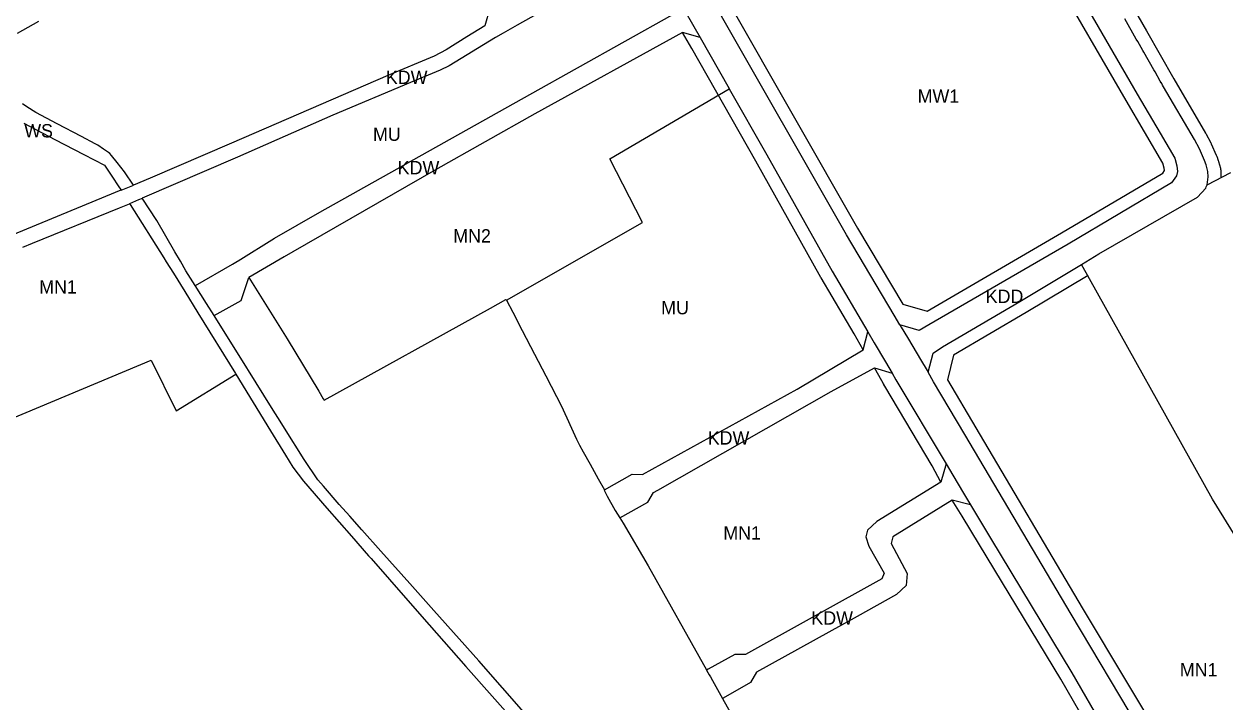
# Model space of a CAD drawing. Extents: x 7435758 to 7439981, y 5550649 to 5554049.
# Drawn here: x 7437381.1 to 7437849, y 5551344.8 to 5551609 of the extents above; entities that cross this region are included whole.
import ezdxf

# ---------------------------------------------------------------- set-up
doc = ezdxf.new("R2010")
doc.units = 0
for name, color, linetype in [('linie_rozgraniczające', 7, 'Continuous'), ('linie_zabudowy_nieprzekraczalne', 7, 'Continuous'), ('oznaczenia_przeznaczen', 7, 'Continuous')]:
    doc.layers.add(name, color=color, linetype=linetype)

msp = doc.modelspace()

# ---------------------------------------------------------------- linework, layer by layer
at = {"layer": 'linie_rozgraniczające'}
for p, q in [((7437608.04, 5551628.18), (7437573.23, 5551608.58)), ((7437791.88, 5551621.44), (7437814.86, 5551581.73)), ((7437562.56, 5551615.13), (7437560.61, 5551608.31)), ((7437638.09, 5551615.13), (7437642.09, 5551608.09)), ((7437701.57, 5551526.92), (7437651.34, 5551614.85)), ((7437578.11, 5551581.52), (7437633.83, 5551612.74)), ((7437814.48, 5551603.18), (7437810.02, 5551611.01)), ((7437560.61, 5551608.31), (7437553.64, 5551604.01)), ((7437567.77, 5551605.51), (7437564.75, 5551603.81)), ((7437573.23, 5551608.58), (7437567.77, 5551605.51)), ((7437637.67, 5551605.66), (7437580.13, 5551574.08)), ((7437644.58, 5551603.71), (7437637.67, 5551605.66)), ((7437642.09, 5551608.09), (7437644.58, 5551603.71)), ((7437553.64, 5551604.01), (7437545.49, 5551599)), ((7437564.75, 5551603.81), (7437546.77, 5551592.74)), ((7437644.58, 5551603.71), (7437655.83, 5551583.9)), ((7437815.05, 5551602.18), (7437814.48, 5551603.18)), ((7437816.99, 5551598.76), (7437815.05, 5551602.18)), ((7437540.86, 5551596.51), (7437522.88, 5551589.02)), ((7437545.49, 5551599), (7437540.86, 5551596.51)), ((7437817.4, 5551598.05), (7437816.99, 5551598.76)), ((7437821.35, 5551591.11), (7437817.4, 5551598.05)), ((7437546.77, 5551592.74), (7437543.25, 5551591.01)), ((7437522.88, 5551589.02), (7437461.88, 5551562.63)), ((7437543.25, 5551591.01), (7437531.66, 5551586.18)), ((7437821.79, 5551590.35), (7437821.35, 5551591.11)), ((7437823.82, 5551586.78), (7437821.79, 5551590.35)), ((7437824.19, 5551586.13), (7437823.82, 5551586.78)), ((7437531.66, 5551586.18), (7437501.44, 5551573.48)), ((7437609.34, 5551556.45), (7437655.88, 5551583.82)), ((7437655.83, 5551583.9), (7437655.88, 5551583.82)), ((7437655.88, 5551583.82), (7437670.53, 5551558.04)), ((7437824.23, 5551586.06), (7437824.19, 5551586.13)), ((7437824.69, 5551585.25), (7437824.23, 5551586.06)), ((7437825.1, 5551584.56), (7437824.69, 5551585.25)), ((7437837.12, 5551563.97), (7437825.1, 5551584.56)), ((7437382.18, 5551576.79), (7437380.45, 5551577.89)), ((7437496.28, 5551535.7), (7437578.11, 5551581.52)), ((7437814.86, 5551581.73), (7437823.8, 5551566.5)), ((7437385.68, 5551574.56), (7437382.18, 5551576.79)), ((7437389.87, 5551572.34), (7437385.68, 5551574.56)), ((7437501.44, 5551573.48), (7437464.28, 5551557.13)), ((7437580.13, 5551574.08), (7437541.41, 5551552.18)), ((7437380.95, 5551570.4), (7437393.08, 5551564.08)), ((7437394.02, 5551570.14), (7437389.87, 5551572.34)), ((7437403.46, 5551565.14), (7437394.02, 5551570.14)), ((7437393.08, 5551564.08), (7437404.43, 5551558.15)), ((7437408.72, 5551562.36), (7437403.46, 5551565.14)), ((7437823.8, 5551566.5), (7437829.53, 5551556.73)), ((7437839.09, 5551560.33), (7437837.12, 5551563.97)), ((7437409.85, 5551561.76), (7437408.72, 5551562.36)), ((7437412.01, 5551560.28), (7437409.85, 5551561.76)), ((7437414.01, 5551558.9), (7437412.01, 5551560.28)), ((7437414.48, 5551558.57), (7437414.01, 5551558.9)), ((7437415.09, 5551557.81), (7437414.48, 5551558.57)), ((7437461.88, 5551562.63), (7437430.21, 5551548.94)), ((7437841.1, 5551555.87), (7437839.09, 5551560.33)), ((7437404.43, 5551558.15), (7437412.38, 5551554.01)), ((7437412.38, 5551554.01), (7437415.49, 5551549.39)), ((7437417.36, 5551554.99), (7437415.09, 5551557.81)), ((7437420.26, 5551551.36), (7437417.36, 5551554.99)), ((7437464.28, 5551557.13), (7437427.1, 5551541.11)), ((7437622, 5551531.63), (7437609.34, 5551556.45)), ((7437670.53, 5551558.04), (7437695.96, 5551512.69)), ((7437829.53, 5551556.73), (7437830.32, 5551553.69)), ((7437841.72, 5551554.12), (7437841.1, 5551555.87)), ((7437842.38, 5551551.59), (7437841.72, 5551554.12)), ((7437415.49, 5551549.39), (7437417.77, 5551546.01)), ((7437423.69, 5551546.25), (7437420.26, 5551551.36)), ((7437541.41, 5551552.18), (7437485.75, 5551520.23)), ((7437830.11, 5551549.81), (7437828.25, 5551547.15)), ((7437830.55, 5551551.56), (7437830.11, 5551549.81)), ((7437830.32, 5551553.69), (7437830.55, 5551551.56)), ((7437842.06, 5551546.41), (7437851.26, 5551551.21)), ((7437842.06, 5551546.41), (7437842.43, 5551549.43)), ((7437842.43, 5551549.43), (7437842.38, 5551551.59)), ((7437417.77, 5551546.01), (7437418.85, 5551544.26)), ((7437418.85, 5551544.26), (7437423.43, 5551546.15)), ((7437423.43, 5551546.15), (7437423.69, 5551546.25)), ((7437430.21, 5551548.94), (7437423.69, 5551546.25)), ((7437828.25, 5551547.15), (7437787.93, 5551523.28)), ((7437838.31, 5551541.54), (7437841.6, 5551545.1)), ((7437841.6, 5551545.1), (7437841.75, 5551545.54)), ((7437841.75, 5551545.54), (7437842.06, 5551546.41)), ((7437418.77, 5551544.23), (7437369.52, 5551523.95)), ((7437418.82, 5551544.25), (7437418.77, 5551544.23)), ((7437418.85, 5551544.26), (7437418.82, 5551544.25)), ((7437425.64, 5551540.48), (7437422.16, 5551539)), ((7437427.04, 5551541.08), (7437425.64, 5551540.48)), ((7437427.1, 5551541.11), (7437427.04, 5551541.08)), ((7437432.81, 5551532.41), (7437427.1, 5551541.11)), ((7437799.93, 5551519.4), (7437838.31, 5551541.54)), ((7437384.42, 5551523.61), (7437418.23, 5551537.33)), ((7437418.23, 5551537.33), (7437422.16, 5551539)), ((7437422.16, 5551539), (7437422.37, 5551538.67)), ((7437422.16, 5551539), (7437422.16, 5551539)), ((7437422.37, 5551538.67), (7437422.38, 5551538.67)), ((7437422.38, 5551538.67), (7437435.56, 5551517.84)), ((7437478.6, 5551525.54), (7437496.28, 5551535.7)), ((7437439.88, 5551520.22), (7437432.81, 5551532.41)), ((7437569.07, 5551501.4), (7437622, 5551531.63)), ((7437720.17, 5551495.53), (7437701.57, 5551526.92)), ((7437380.59, 5551522), (7437384.42, 5551523.61)), ((7437464.55, 5551516.73), (7437478.6, 5551525.54)), ((7437787.93, 5551523.28), (7437733.69, 5551491.76)), ((7437435.56, 5551517.84), (7437435.56, 5551517.84)), ((7437435.56, 5551517.84), (7437436.51, 5551516.34)), ((7437442, 5551516.56), (7437439.88, 5551520.22)), ((7437444.13, 5551512.88), (7437442, 5551516.56)), ((7437462.3, 5551515.43), (7437464.27, 5551516.57)), ((7437464.27, 5551516.57), (7437464.55, 5551516.73)), ((7437482.38, 5551518.3), (7437468.63, 5551510.25)), ((7437485.75, 5551520.23), (7437482.38, 5551518.3)), ((7437793.08, 5551515.29), (7437799.93, 5551519.4)), ((7437436.51, 5551516.34), (7437439.31, 5551511.91)), ((7437439.31, 5551511.91), (7437443.68, 5551504.82)), ((7437447.8, 5551507.06), (7437444.13, 5551512.88)), ((7437447.87, 5551507.1), (7437462.3, 5551515.43)), ((7437695.96, 5551512.69), (7437709.87, 5551489)), ((7437769.04, 5551500.85), (7437793.08, 5551515.29)), ((7437844.14, 5551423.82), (7437793.08, 5551515.29)), ((7437447.8, 5551507.06), (7437447.87, 5551507.1)), ((7437452.15, 5551500.11), (7437447.8, 5551507.06)), ((7437465.61, 5551501.21), (7437468.63, 5551510.25)), ((7437468.63, 5551510.25), (7437469.93, 5551508.17)), ((7437469.93, 5551508.17), (7437469.93, 5551508.16)), ((7437469.93, 5551508.16), (7437483.59, 5551486.32)), ((7437443.68, 5551504.82), (7437448.84, 5551496.44)), ((7437452.15, 5551500.1), (7437452.15, 5551500.11)), ((7437455.1, 5551495.38), (7437452.15, 5551500.1)), ((7437455.1, 5551495.38), (7437465.61, 5551501.21)), ((7437498, 5551462.41), (7437562.78, 5551498.27)), ((7437562.78, 5551498.27), (7437568.83, 5551501.62)), ((7437568.83, 5551501.62), (7437568.93, 5551501.68)), ((7437568.93, 5551501.68), (7437568.96, 5551501.62)), ((7437568.96, 5551501.62), (7437569.07, 5551501.4)), ((7437569.07, 5551501.4), (7437571.51, 5551496.7)), ((7437738.9, 5551483.22), (7437769.04, 5551500.85)), ((7437448.84, 5551496.44), (7437448.85, 5551496.43)), ((7437448.85, 5551496.43), (7437463.41, 5551472.81)), ((7437467.84, 5551475.04), (7437455.1, 5551495.38)), ((7437571.51, 5551496.7), (7437575.21, 5551489.57)), ((7437722.37, 5551491.81), (7437720.17, 5551495.53)), ((7437575.21, 5551489.57), (7437580.02, 5551480.3)), ((7437708.02, 5551482.1), (7437709.87, 5551489)), ((7437709.87, 5551489), (7437712.39, 5551484.71)), ((7437722.37, 5551491.81), (7437722.89, 5551490.94)), ((7437729.92, 5551489.6), (7437722.37, 5551491.81)), ((7437722.89, 5551490.94), (7437725.29, 5551486.88)), ((7437733.69, 5551491.76), (7437729.92, 5551489.6)), ((7437483.59, 5551486.32), (7437495.92, 5551465.91)), ((7437712.39, 5551484.71), (7437716.73, 5551477.32)), ((7437725.29, 5551486.88), (7437725.68, 5551486.23)), ((7437725.68, 5551486.23), (7437730.4, 5551478.26)), ((7437580.02, 5551480.3), (7437584.4, 5551471.85)), ((7437682.35, 5551466.73), (7437708.02, 5551482.1)), ((7437733.34, 5551473.3), (7437735.26, 5551480.73)), ((7437735.26, 5551480.73), (7437738.9, 5551483.22)), ((7437339.37, 5551439.87), (7437430.62, 5551478.01)), ((7437430.62, 5551478.01), (7437440.33, 5551458.26)), ((7437468.5, 5551473.97), (7437467.84, 5551475.04)), ((7437695.61, 5551465.77), (7437712.43, 5551474.97)), ((7437712.43, 5551474.97), (7437719.31, 5551472.93)), ((7437716.73, 5551477.32), (7437719.31, 5551472.93)), ((7437730.4, 5551478.26), (7437732.96, 5551473.93)), ((7437440.33, 5551458.26), (7437463.55, 5551472.55)), ((7437463.41, 5551472.81), (7437463.56, 5551472.56)), ((7437463.55, 5551472.55), (7437463.56, 5551472.56)), ((7437463.56, 5551472.56), (7437477.15, 5551450.5)), ((7437477.53, 5551459.57), (7437468.5, 5551473.97)), ((7437584.4, 5551471.85), (7437588.57, 5551463.81)), ((7437719.31, 5551472.93), (7437720.79, 5551470.41)), ((7437720.79, 5551470.41), (7437740.34, 5551437.61)), ((7437732.96, 5551473.93), (7437733.34, 5551473.3)), ((7437735.5, 5551469.63), (7437733.34, 5551473.3)), ((7437747.69, 5551449.05), (7437735.5, 5551469.63)), ((7437495.92, 5551465.91), (7437497.67, 5551462.96)), ((7437622.11, 5551433.49), (7437682.35, 5551466.73)), ((7437628.08, 5551427.37), (7437695.61, 5551465.77)), ((7437497.67, 5551462.96), (7437498, 5551462.41)), ((7437588.57, 5551463.81), (7437590.39, 5551460.3)), ((7437590.39, 5551460.3), (7437592.55, 5551455.6)), ((7437481.55, 5551453.16), (7437477.53, 5551459.57)), ((7437592.55, 5551455.6), (7437594.43, 5551451.51)), ((7437482.57, 5551451.53), (7437481.55, 5551453.16)), ((7437490.26, 5551439.33), (7437482.57, 5551451.53)), ((7437594.43, 5551451.51), (7437596.37, 5551447.27)), ((7437477.15, 5551450.5), (7437482.92, 5551441.05)), ((7437596.37, 5551447.27), (7437597.49, 5551444.84)), ((7437789.1, 5551378.96), (7437747.69, 5551449.05)), ((7437597.49, 5551444.84), (7437598.94, 5551442.27)), ((7437598.94, 5551442.27), (7437601.67, 5551437.43)), ((7437482.92, 5551441.05), (7437485.77, 5551436.37)), ((7437495.56, 5551431.41), (7437490.26, 5551439.33)), ((7437601.67, 5551437.43), (7437604.73, 5551431.76)), ((7437740.34, 5551437.61), (7437738.36, 5551430.44)), ((7437740.34, 5551437.61), (7437742.94, 5551433.25)), ((7437485.77, 5551436.37), (7437490, 5551430.8)), ((7437607.27, 5551427.5), (7437618.01, 5551433.54)), ((7437618.01, 5551433.54), (7437622.11, 5551433.49)), ((7437742.94, 5551433.25), (7437747.16, 5551426.17)), ((7437490, 5551430.8), (7437499.01, 5551420.3)), ((7437497.7, 5551428.94), (7437495.56, 5551431.41)), ((7437503.92, 5551421.75), (7437497.7, 5551428.94)), ((7437604.73, 5551431.76), (7437607.27, 5551427.5)), ((7437607.27, 5551427.5), (7437607.08, 5551427.39)), ((7437738.36, 5551430.44), (7437713.37, 5551415.12)), ((7437607.08, 5551427.39), (7437608.34, 5551425.05)), ((7437608.34, 5551425.05), (7437611.46, 5551419.38)), ((7437624.13, 5551422.64), (7437626.4, 5551426.47)), ((7437626.4, 5551426.47), (7437628.08, 5551427.37)), ((7437742.73, 5551423.43), (7437719.6, 5551409.14)), ((7437749.88, 5551421.6), (7437742.73, 5551423.43)), ((7437747.16, 5551426.17), (7437749.88, 5551421.6)), ((7437946.07, 5551258.39), (7437844.14, 5551423.82)), ((7437499.01, 5551420.3), (7437508.62, 5551409.43)), ((7437507.97, 5551417.23), (7437503.92, 5551421.75)), ((7437611.46, 5551419.38), (7437613.22, 5551416.56)), ((7437613.29, 5551416.6), (7437624.13, 5551422.64)), ((7437749.88, 5551421.6), (7437757.63, 5551408.61)), ((7437512.75, 5551411.9), (7437507.97, 5551417.23)), ((7437613.22, 5551416.56), (7437613.29, 5551416.6)), ((7437613.22, 5551416.56), (7437614.54, 5551414.45)), ((7437614.54, 5551414.45), (7437624.22, 5551397.83)), ((7437713.37, 5551415.12), (7437709.77, 5551411.73)), ((7437508.62, 5551409.43), (7437515.35, 5551401.82)), ((7437520.15, 5551403.52), (7437512.75, 5551411.9)), ((7437709.77, 5551411.73), (7437709.12, 5551409.21)), ((7437709.12, 5551409.21), (7437710.27, 5551405.52)), ((7437719.6, 5551409.14), (7437718.96, 5551406.62)), ((7437710.27, 5551405.52), (7437716.18, 5551395.03)), ((7437718.96, 5551406.62), (7437725.17, 5551394.9)), ((7437757.63, 5551408.61), (7437789.38, 5551356.19)), ((7437515.35, 5551401.82), (7437516.3, 5551400.74)), ((7437516.3, 5551400.74), (7437523.48, 5551392.49)), ((7437531.34, 5551390.99), (7437520.15, 5551403.52)), ((7437624.22, 5551397.83), (7437647.01, 5551357.31)), ((7437716.18, 5551395.03), (7437715.28, 5551392.75)), ((7437725.17, 5551394.9), (7437724.86, 5551390.15)), ((7437523.48, 5551392.49), (7437536.04, 5551378.06)), ((7437540.77, 5551380.43), (7437531.34, 5551390.99)), ((7437715.28, 5551392.75), (7437662.21, 5551363.27)), ((7437724.86, 5551390.15), (7437721.01, 5551386.75)), ((7437721.01, 5551386.75), (7437705.65, 5551378.14)), ((7437536.04, 5551378.06), (7437553.16, 5551358.57)), ((7437558.29, 5551360.79), (7437540.77, 5551380.43)), ((7437705.65, 5551378.14), (7437666.54, 5551356.47)), ((7437841.65, 5551291.1), (7437789.1, 5551378.96)), ((7437658.02, 5551363.32), (7437647.67, 5551357.57)), ((7437662.21, 5551363.27), (7437658.02, 5551363.32)), ((7437553.16, 5551358.57), (7437579.45, 5551329.21)), ((7437576.75, 5551339.77), (7437558.29, 5551360.79)), ((7437647.01, 5551357.31), (7437647.06, 5551357.23)), ((7437647.67, 5551357.57), (7437647.06, 5551357.23)), ((7437647.06, 5551357.23), (7437648.08, 5551355.42)), ((7437648.08, 5551355.42), (7437648.55, 5551354.57)), ((7437648.55, 5551354.57), (7437649.32, 5551353.19)), ((7437649.32, 5551353.19), (7437653.21, 5551346.21)), ((7437666.54, 5551356.47), (7437664.13, 5551352.42)), ((7437789.38, 5551356.19), (7437807.13, 5551325.42)), ((7437664.13, 5551352.42), (7437653.43, 5551346.33)), ((7437653.43, 5551346.33), (7437653.21, 5551346.21)), ((7437653.21, 5551346.21), (7437656.2, 5551340.85))]:
    msp.add_line(p, q, dxfattribs=at)
at = {"layer": 'linie_zabudowy_nieprzekraczalne'}
for points in [[(7437653.08, 5551622.16), (7437656.22, 5551616.38), (7437705.89, 5551529.43), (7437723.44, 5551499.81), (7437733, 5551497.15), (7437785.39, 5551527.59), (7437824.77, 5551550.9), (7437825.49, 5551551.92), (7437825.39, 5551552.78), (7437824.87, 5551554.79), (7437810.55, 5551579.2), (7437810.53, 5551579.23), (7437781.56, 5551629.29), (7437756.5, 5551670.46), (7437753.06, 5551676.12)], [(7437811.73, 5551618.1), (7437818.39, 5551606.38), (7437829.11, 5551587.61), (7437841.44, 5551566.49), (7437841.51, 5551566.36), (7437841.51, 5551566.35), (7437843.49, 5551562.72), (7437843.63, 5551562.43), (7437843.66, 5551562.38), (7437845.66, 5551557.91), (7437845.76, 5551557.66), (7437845.8, 5551557.55), (7437846.43, 5551555.81), (7437846.49, 5551555.61), (7437846.56, 5551555.39), (7437847.22, 5551552.86), (7437847.24, 5551552.76), (7437847.31, 5551552.44), (7437847.36, 5551552.12), (7437847.38, 5551551.79), (7437847.38, 5551551.69), (7437847.43, 5551549.41)], [(7437386.72, 5551609.96), (7437378.45, 5551605.28)], [(7437708.02, 5551482.1), (7437704.5, 5551488.27), (7437691.65, 5551510.16), (7437691.6, 5551510.25), (7437666.17, 5551555.59), (7437641.24, 5551599.46), (7437637.67, 5551605.66)], [(7437795.66, 5551511), (7437771.62, 5551496.56), (7437771.59, 5551496.55), (7437771.57, 5551496.53), (7437743.24, 5551479.97), (7437740.85, 5551470.41), (7437751.99, 5551451.59), (7437751.99, 5551451.59), (7437793.4, 5551381.52), (7437845.93, 5551293.68)], [(7437716.47, 5551467.88), (7437712.43, 5551474.97)], [(7437716.47, 5551467.88), (7437716, 5551468.69)], [(7437738.36, 5551430.44), (7437734.95, 5551436.88), (7437716.49, 5551467.85), (7437716.47, 5551467.88)], [(7437945.38, 5551110.68), (7437944.16, 5551111.91), (7437944.1, 5551111.98), (7437943.99, 5551112.09), (7437920.13, 5551138.79), (7437920.01, 5551138.92), (7437904.28, 5551157.81), (7437904.08, 5551158.06), (7437903.98, 5551158.2), (7437894.29, 5551172.45), (7437894.2, 5551172.59), (7437880.46, 5551194.33), (7437880.46, 5551194.33), (7437860.28, 5551226.39), (7437860.24, 5551226.45), (7437825.19, 5551284.1), (7437825.13, 5551284.2), (7437785.07, 5551353.65), (7437753.35, 5551406.01), (7437753.34, 5551406.04), (7437746.65, 5551417.27), (7437742.73, 5551423.43)]]:
    msp.add_lwpolyline(points, dxfattribs=at)

# ---------------------------------------------------------------- texts
at = {"layer": 'oznaczenia_przeznaczen'}
for s, p in [('KDW', (7437522.05, 5551585.65)), ('MW1', (7437729.26, 5551578.32)), ('WS', (7437381.14, 5551564.82)), ('MU', (7437517.02, 5551563.48)), ('KDW', (7437526.66, 5551550.44)), ('MN2', (7437548.31, 5551523.87)), ('MN1', (7437386.99, 5551503.98)), ('KDD', (7437755.79, 5551500.29)), ('MU', (7437629.33, 5551495.88)), ('KDW', (7437647.47, 5551445.12)), ('MN1', (7437653.56, 5551408.1)), ('KDW', (7437687.85, 5551374.94)), ('MN1', (7437831.45, 5551354.76))]:
    msp.add_text(s, height=5.2, dxfattribs=at).set_placement(p)

doc.saveas('drawing.dxf')
